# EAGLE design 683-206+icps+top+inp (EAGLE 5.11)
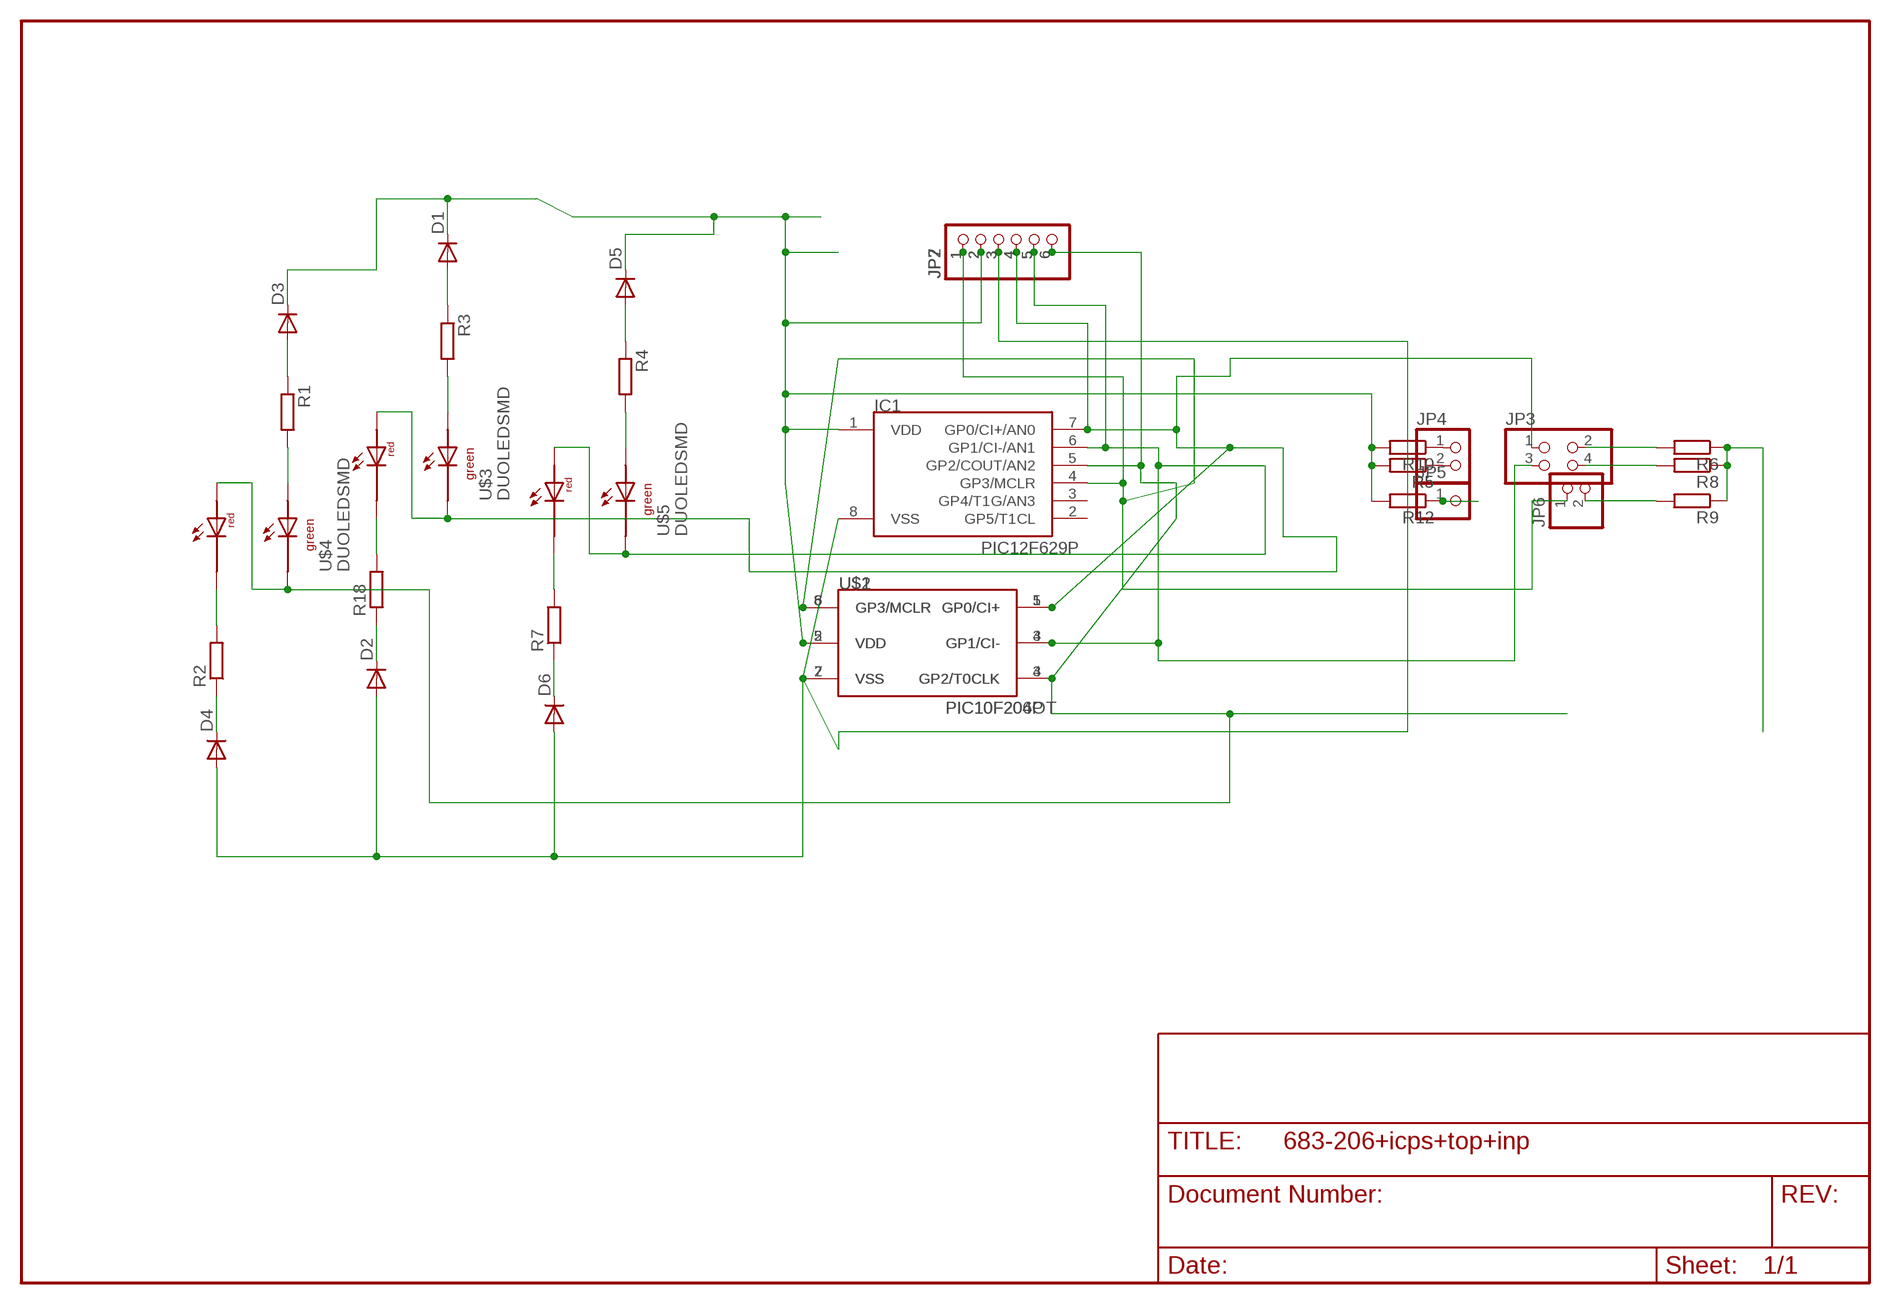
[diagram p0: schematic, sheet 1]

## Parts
D1  DIODE-MINIMELF  [MINIMELF]
D2  DIODE-MINIMELF  [MINIMELF]
D3  DIODE-MINIMELF  [MINIMELF]
D4  DIODE-MINIMELF  [MINIMELF]
D5  DIODE-MINIMELF  [MINIMELF]
D6  DIODE-MINIMELF  [MINIMELF]
IC1  PIC12F629P  [DIL8]
JP2  PINHD-1X6  [1X06]
JP3  PINHD-2X2  [2X02]
JP4  PINHD-1X2  [1X02]
JP5  PINHD-1X1  [1X01]
JP6  PINHD-1X2  [1X02]
JP7  PINHD-1X6  [1X06]
R1  R-EU_R1206  [R1206]
R2  R-EU_R1206  [R1206]
R3  R-EU_R1206  [R1206]
R4  R-EU_R1206  [R1206]
R5  R-EU_R1206  [R1206]
R6  R-EU_R1206  [R1206]
R7  R-EU_R1206  [R1206]
R8  R-EU_R1206  [R1206]
R9  R-EU_R1206  [R1206]
R10  R-EU_R1206  [R1206]
R12  R-EU_R1206  [R1206]
R18  R-EU_R1206  [R1206]
U$1  PIC10F206P  [DIL8]
U$2  PIC10F204OT  [SOT23-6]
U$3  DUOLEDSMD  [DUOLEDSMD]
U$4  DUOLEDSMD  [DUOLEDSMD]
U$5  DUOLEDSMD  [DUOLEDSMD]

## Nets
GP0: IC1.7(GP0/CI+/AN0) JP2.4 JP3.1 JP7.4 U$1.5(GP0/CI+) U$2.1(GP0/CI+) U$3.ARED U$3.CGRN
GP1: IC1.6(GP1/CI-/AN1) JP2.5 JP3.3 JP7.5 U$1.4(GP1/CI-) U$2.3(GP1/CI-) U$5.ARED U$5.CGRN
GP2: IC1.5(GP2/COUT/AN2) JP2.6 JP7.6 U$1.3(GP2/T0CLK) U$2.4(GP2/T0CLK) U$4.ARED U$4.CGRN
GP3: IC1.4(GP3/MCLR) JP2.1 JP6.1 JP7.1 U$1.8(GP3/MCLR) U$2.6(GP3/MCLR)
N$3: R3.2 U$3.AGRN
N$6: R18.2 U$3.CRED
N$7: D2.C R18.1
N$8: D3.A R1.1
N$11: D1.A R3.1
N$14: R6.1 R8.1 R9.1
N$15: JP4.2 R5.1
N$16: JP4.1 R10.1
N$18: JP5.1 R12.1
N$20: R1.2 U$4.AGRN
N$21: D4.C R2.1
N$22: JP6.2 R9.2
N$23: R2.2 U$4.CRED
N$24: JP3.4 R8.2
N$25: JP3.2 R6.2
N$26: D5.A R4.1
N$30: R4.2 U$5.AGRN
N$31: D6.C R7.1
N$32: R7.2 U$5.CRED
VDD: D1.C D3.C D5.C IC1.1(VDD) JP2.2 JP7.2 R5.2 R10.2 R12.2 U$1.2(VDD) U$2.5(VDD)
VSS: D2.A D4.A D6.A IC1.8(VSS) JP2.3 JP7.3 U$1.7(VSS) U$2.2(VSS)
Unconnected: IC1.2(GP5/T1CL) IC1.3(GP4/T1G/AN3)

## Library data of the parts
D1-D6 = diode:DIODE-: DIODE
IC1 = microchip-5:PIC12F6*: uPC nW 1k Program Flash memory 2x Timer Comparator 10b A/D converter/ 4xIN
JP2 JP7 = pinhead:PINHD-1X6: PIN HEADER
JP3 = pinhead(2):PINHD-2X2: PIN HEADER
JP4 JP6 = pinhead(2):PINHD-1X2: PIN HEADER
JP5 = pinhead(2):PINHD-1X1: PIN HEADER
R1-R4 R7 R18 = rcl:R-EU_: RESISTOR, European symbol
R5 R6 R8-R10 R12 = rcl-2:R-EU_: RESISTOR, European symbol
U$1 U$2 = microchip-5:PIC10F2*: uPC nW 0,25/0,5k Program Flash memory Comparator
U$3-U$5 = led:DUOLEDSMD

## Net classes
0 default: width 0.3 mm, drill 0.6 mm, clearance 0.2 mm
1 power: width 0.4 mm, drill 0.6 mm, clearance 0.2 mm

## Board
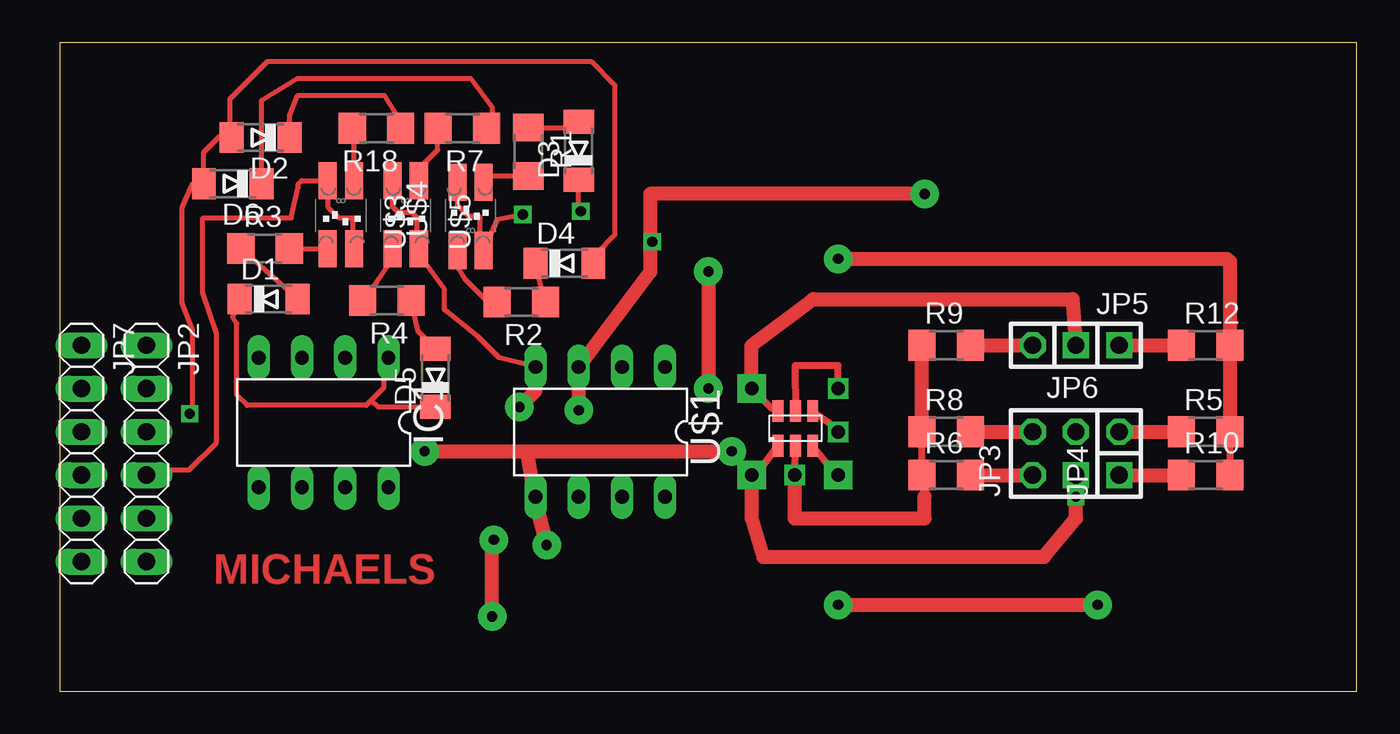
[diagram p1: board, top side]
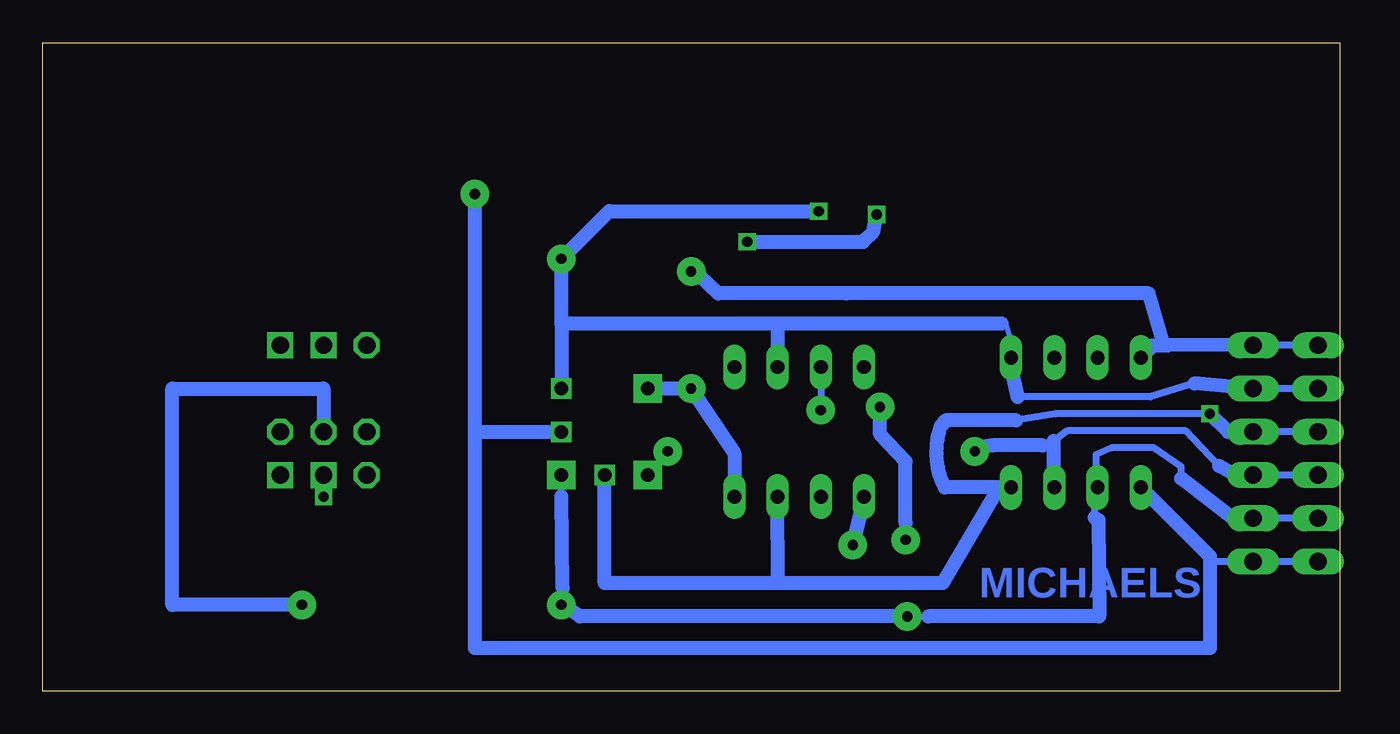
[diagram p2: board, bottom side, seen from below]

Size 76.2 x 38.1 mm. Coordinates in mm from the lower left corner, seen from the top.
Outline: 0,0 76.2,0 76.2,38.1 0,38.1 0,0
Copper layers (1*16): Top 0.035mm / dielectric 1.5mm / Bottom 0.035mm
Design rules "default": minimum track width 10mil, minimum drill 24mil, track to track 8mil, track to pad 8mil, pad to pad 8mil, via to via 8mil, smd to smd 8mil, copper to edge 40mil, drill to drill 8mil, minimum pad ring 10mil, minimum via ring 8mil, stop-mask expansion 4mil, vias tented up to drill 0mil, thermal gap 10mil

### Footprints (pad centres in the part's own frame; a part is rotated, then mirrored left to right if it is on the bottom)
MINIMELF = smd 1.4 x 1.8: A 1.7,0; C -1.7,0
DIL8 = drill 0.813 long: 1 -3.81,-3.81; 2 -1.27,-3.81; 3 1.27,-3.81; 4 3.81,-3.81; 5 3.81,3.81; 6 1.27,3.81; 7 -1.27,3.81; 8 -3.81,3.81
1X06 = drill 1.016 long: 1 -6.35,0; 2 -3.81,0; 3 -1.27,0; 4 1.27,0; 5 3.81,0; 6 6.35,0
2X02 = drill 1.016 square: 1 -1.27,-1.27 | drill 1.016 octagon: 2 -1.27,1.27; 3 1.27,-1.27; 4 1.27,1.27
1X02 = drill 1.016 square: 1 -1.27,0 | drill 1.016 octagon: 2 1.27,0
1X01 = drill 1.016 square: 1 0,0
R1206 = smd 1.6 x 1.803: 1 -1.422,0; 2 1.422,0
SOT23-6 = smd 0.635 x 1.27: 1 -1.016,-1.016; 2 0,-1.016; 3 1.016,-1.016; 4 1.016,1.016; 5 0,1.016; 6 -1.016,1.016
DUOLEDSMD = smd 1.067 x 2.184: AGRN 0.77,1.95; ARED -0.77,1.95; CGRN 0.77,-2.05; CRED -0.77,-2.05

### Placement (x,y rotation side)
D1  12.27,23.04 0 top
D2  11.8,32.52 180 top
D3  30.48,31.75 90 top
D4  29.64,25.14 0 top
D5  22.06,18.41 90 top
D6  10.16,29.81 180 top
IC1  15.49,15.79 180 top
JP2  5.08,13.97 270 top
JP3  58.42,13.97 90 top
JP4  62.23,13.97 90 top
JP5  62.23,20.32 0 top
JP6  58.42,20.32 180 top
JP7  1.27,13.97 270 top
R1  27.52,31.69 270 top
R2  27.11,22.87 180 top
R3  12.06,26 0 top
R4  19.21,22.96 180 top
R5  67.31,15.24 0 top
R6  52.07,12.7 0 top
R7  23.65,33.07 180 top
R8  52.07,15.24 0 top
R9  52.07,20.32 0 top
R10  67.31,12.7 0 top
R12  67.31,20.32 0 top
R18  18.6,33.07 180 top
U$1  31.75,15.24 180 top
U$2  43.21,15.44 0 top
U$3  16.51,27.94 180 top
U$4  24.13,27.94 0 top
U$5  20.32,27.94 180 top

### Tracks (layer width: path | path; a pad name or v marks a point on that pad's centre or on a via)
GP0  (via drill 0.6, 0.6 pad 1.68, 0.8 pad 1.68)
  Top 0.305: JP2.4 5.38,13 7.6,13 9.2,14.6 9.2,21 8.4,23.4 8.4,27.8 13.6,27.8 14,29.6 14,29.8 14.19,29.99 U$3.CGRN 15.74,28.46 16.4,27.8 17.2,27.8 17.2,26.07 U$3.ARED
  Top 0.406: U$2.1 41.06,12.92 v40.64,12.7 | v21.43,14.1 22.23,14.07
  Top 0.813: v21.43,14.1 27.4,14.1 | 27.4,14.1 v39.47,14.1 | v59.69,11.43 59.69,10.16 57.82,7.89 41.31,7.89 40.64,10.16 v40.64,12.7 | v28.6,8.6 27.9,11.2 27.4,14.1
  Bottom 0.406: 6.11,12.7 JP2.4 JP7.4 | 7.09,13.24 9.05,15.3 16.01,15.3 16.81,14.7 17.45,14.44 | 16.81,12.03 IC1.7 | v39.47,14.1 v40.64,12.7 | 27.9,11.39 U$1.5 | v59.69,11.43 JP3.1
  Bottom 0.813: 6.11,12.7 7.09,13.24 | 16.81,14.7 16.81,12.03 | v21.43,14.1 21.46,14.27 20.39,14.44 17.45,14.44 | v28.6,8.6 27.9,11.39
GP1  (via drill 0.6 pad 1.68, 0.8 pad 1.68)
  Top 0.305: U$5.CGRN 19.55,28.45 19.9,28.1 20.7,28.1 21,27.8 21,26.08 U$5.ARED 21.09,25.71 22.6,23.6 22.6,22.4 24.6,20.8 25.79,19.6 U$1.4
  Top 0.406: U$2.3 45.23,13.19 v45.72,12.7 | 25.4,8.6 v25.5,8.9 | v27,16.7 26.9,16.6
  Top 0.813: v25.4,4.4 25.4,8.6 | v45.72,5.08 v60.96,5.08 | U$1.4 27.94,17.64 v27,16.7
  Bottom 0.406: 6.27,10.16 JP2.5 JP7.5 | 9.31,12.5 9.31,13.2 10.91,14.3 13.41,14.3 14.31,13.9 14.31,12.07 IC1.6 14.41,11.79 14.41,10.2 | 45.72,11.43 v45.72,12.7 | v45.72,5.08 45.72,6.03 45.65,6.06 | v25.5,8.9 25.5,9.9 | 24.17,4.4 25.46,4.26 v25.4,4.4
  Bottom 0.813: 6.27,10.16 9.31,12.5 | 45.65,6.06 45.72,11.43 | 24.17,4.4 14.13,4.4 14.17,10.07 14.41,10.2 | 25.5,9.9 25.5,13.5 27,15.11 v27,16.7 | JP3.3 59.69,17.78 68.58,17.78 68.58,5.08 v60.96,5.08 | v25.4,4.4 44.63,4.4 v45.72,5.08
GP2  (via drill 0.6, 0.6 pad 1.68, 0.8)
  Top 0.305: U$4.ARED 23.36,28.54 24,27.9 24.6,27.9 24.7,27.8 24.7,26.5 24.6,26.4 24.6,26.19 U$4.CGRN 25.69,27.69 v27.2,28 | 34.68,26.4 v34.8,26.4
  Top 0.406: U$2.4 45.23,15.73 v45.72,15.24
  Top 0.813: v50.8,29.21 34.68,29.21 34.68,26.4 34.68,24.63 U$1.3 v30.48,16.51
  Bottom 0.406: 7.62,7.92 7.62,7.62 JP2.6 JP7.6 | IC1.5 11.28,11.58 11.43,11.43 | U$1.3 v30.48,16.51
  Bottom 0.813: 50.8,15.24 v45.72,15.24 | 50.8,15.24 50.8,2.54 7.62,2.54 7.62,7.62 | 7.62,7.92 11.28,11.58 | 50.8,15.24 v50.8,29.21 | v27.2,28 27.4,27 28,26.4 v34.8,26.4
GP3  (via drill 0.6 pad 1.68, 0.8 pad 1.68)
  Top 0.406: U$2.6 41.76,16.66 v40.64,17.78
  Top 0.813: v38.1,24.66 v38.1,17.78 | v40.64,17.78 40.64,20.32 44.25,23.03 59.49,23.03 JP6.1
  Bottom 0.305: 29,23.37 28.8,23.57
  Bottom 0.406: 10.11,20.3 8.19,20.32 JP2.1 JP7.1
  Bottom 0.813: v40.64,17.78 v38.1,17.78 35.56,13.97 U$1.8 | v38.1,24.66 37.6,24.4 36.51,23.37 29,23.37 11.22,23.37 10.32,20.36 JP2.1 | 10.11,20.3 10.98,20.3 IC1.4 10.96,20.32 10.16,20.32
N$3
  Top 0.305: R3.2 arc90 13.29,25.99 U$3.AGRN
N$6
  Top 0.305: U$3.CRED 17.28,32.97 R18.2
N$7
  Top 0.305: D2.C 13.5,33.82 13.97,35 19.05,35 20.32,33.02 20.07,33.02 R18.1
N$8
  Top 0.305: R1.1 30.14,33.11 D3.A
N$11
  Top 0.305: D1.A R3.1
N$14
  Top 0.406: R6.1 R8.1
  Top 0.813: R8.1 R9.1
N$15
  Top 0.813: JP4.2 R5.1
N$16
  Top 0.406: R10.1 66.04,12.7
  Top 0.813: JP4.1 R10.1
N$18
  Top 0.813: JP5.1 R12.1
N$20
  Top 0.305: R1.2 25.28,30.27 U$4.AGRN
N$21
  Top 0.305: R2.1 28.13,24.33 D4.C
N$22
  Top 0.813: R9.2 JP6.2
N$23
  Top 0.305: R2.2 25.13,22.87 23.8,24.2 23.2,25.2 23.2,25.73 U$4.CRED
N$24
  Top 0.813: R8.2 JP3.4
N$25
  Top 0.813: R6.2 JP3.2
N$26
  Top 0.305: R4.1 21.03,21.14 D5.A
N$30
  Top 0.305: R4.2 18.59,23.99 19.4,25.2 19.4,25.84 U$5.AGRN
N$31
  Top 0.305: D6.C 11.86,34.72 13.97,36 24.13,36 25.4,34.29 25.4,33.4 R7.1
N$32
  Top 0.305: U$5.CRED 21.09,30.69 22.2,31.8 22.2,33.04 R7.2
VDD  (via drill 0.6, 0.6 pad 1.68, 0.8)
  Top 0.305: D3.C 30.48,28.32 v30.6,28.2 | D1.C 10.16,21.96 10.4,21.6 10.4,17.4 11,16.8 18,16.8 18.3,17.1 | 18.3,17.1 19.03,17.84 19.03,19.33 IC1.1 | D5.C 18.69,16.71 18.3,17.1
  Top 0.406: U$2.5 43.2,19.13 45.72,19.13 v45.72,17.78 | 68.58,25.4 68.73,25.25 | R5.2 R10.2
  Top 0.813: 68.73,25.25 R12.2 R5.2 | v45.72,25.4 68.58,25.4
  Bottom 0.305: 19.85,21.59 19.65,21.69 19.05,19.85 IC1.1 19.3,18.69 19.21,18.6
  Bottom 0.406: 8.53,18.08 11.11,17.3 18.91,17.3 | JP7.2 JP2.2
  Bottom 0.813: JP2.2 8.53,18.08 | 18.91,17.3 19.21,18.6 | 45.72,21.59 v45.72,17.78 | 33.02,21.59 45.72,21.59 | 19.85,21.59 33.02,21.59 | 45.72,21.59 v45.72,25.4 42.92,28.2 v30.6,28.2 | 33.02,21.59 U$1.2
VSS  (via drill 0.6, 0.8)
  Top 0.305: D4.A 31.54,25.74 32.6,26.8 32.6,35.6 31.2,37 12.2,37 10,34.8 10,32.62 D2.A 10.02,32.6 9.4,32.6 8.46,31.66 D6.A 7.81,29.81 7.2,28.4 7.2,22.8 7.8,21.2 7.8,16.49 v7.62,16.31
  Top 0.406: v43.18,12.7 U$2.2 | 50.8,11.43 50.65,11.58
  Top 0.813: 50.8,11.43 50.8,10.16 43.18,10.16 v43.18,12.7
  Bottom 0.406: v7.62,16.31 16.68,16.3 19,15.91 | JP7.3 JP2.3
  Bottom 0.813: IC1.8 20.01,11.98 | 20.01,11.98 23.2,11.98 arc47 23.41,15.59 23.41,15.6 23.27,15.74 23.16,15.91 19,15.91 | 20.01,11.98 23.33,6.35 33,6.35 | 33,6.35 43.18,6.35 v43.18,12.7 | 33,6.35 U$1.7 | JP2.3 6.55,15.24 v7.62,16.31

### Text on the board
Top: MICHAELS
Bottom: MICHAELS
